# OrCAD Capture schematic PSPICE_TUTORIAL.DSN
size A
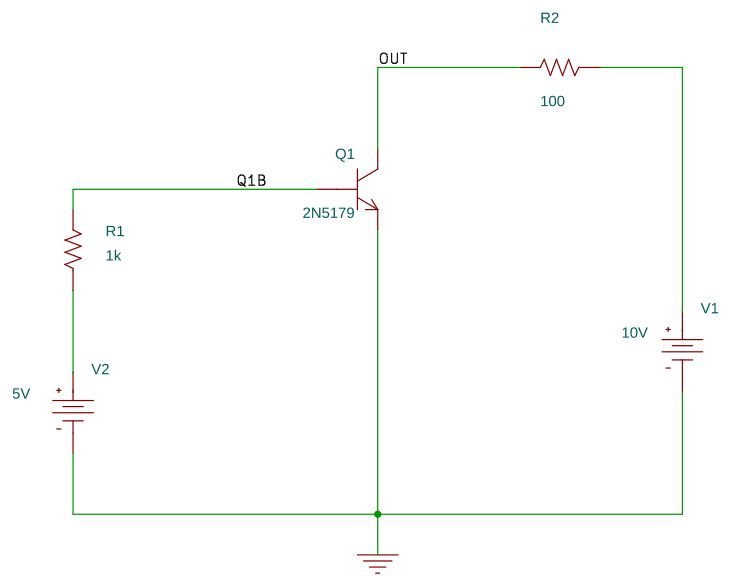
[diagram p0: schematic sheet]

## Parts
Q1  2N5179  [TO72]
R1  1k  [AXRC05]
R2  100  [AXRC05]
V1  VDC
V2  VDC

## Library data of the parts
Q1 = 2N5179
R1 R2 = R
V1 = VDC: DC: 10V
V2 = VDC: DC: 5V

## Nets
0: Q1.1(E) V1.1(-) V2.1(-)
OUT: Q1.3(C) R2.2
Q1B: Q1.2(B) R1.2
N00252: R1.1 V2.0(+)
N00376: R2.1 V1.0(+)
